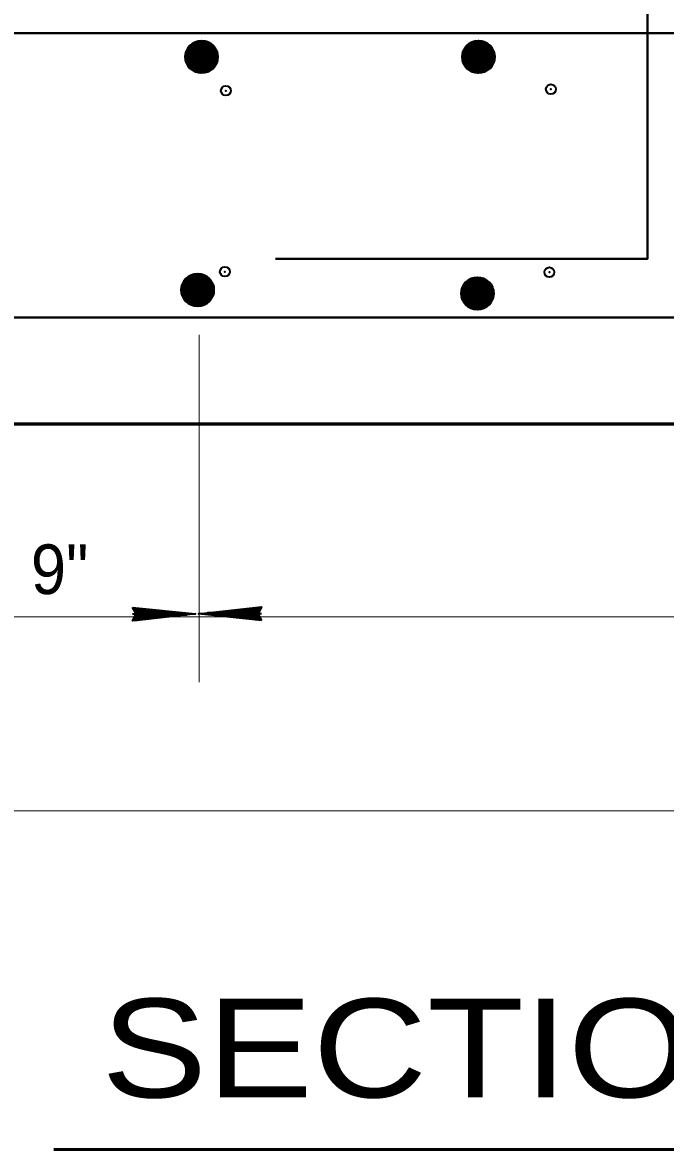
# Model space of a CAD drawing. Extents: x 4.49 to 7.69, y 0.28 to 2.27.
# Drawn here: x 5.8557 to 5.9637, y 1.2921 to 1.4815 of the extents above; entities that cross this region are included whole.
import ezdxf
from ezdxf.enums import TextEntityAlignment as Align

# ---------------------------------------------------------------- set-up
doc = ezdxf.new("R2010")
doc.units = 0
doc.header["$LTSCALE"] = 0.0033
doc.header["$PDMODE"] = 32
doc.header["$PDSIZE"] = 0.00165
doc.layers.add('1', color=7, linetype='Continuous', lineweight=35)

msp = doc.modelspace()

# ---------------------------------------------------------------- linework, layer by layer
at = {"layer": '1', "lineweight": 40}
for p, q in [((5.836083, 1.479667), (6.217, 1.479667)), ((5.883667, 1.47725), (5.88825, 1.475083)), ((5.884, 1.47725), (5.887917, 1.476583)), ((5.884083, 1.477583), (5.887917, 1.476917)), ((5.886, 1.47675), (5.887333, 1.47775)), ((5.888083, 1.476917), (5.886833, 1.478083)), ((5.930167, 1.47725), (5.93475, 1.475083)), ((5.9305, 1.47725), (5.934417, 1.476583)), ((5.930583, 1.477583), (5.934417, 1.476917)), ((5.9325, 1.47675), (5.933833, 1.47775)), ((5.934583, 1.476917), (5.933333, 1.478083)), ((5.883667, 1.475417), (5.887583, 1.474667)), ((5.88375, 1.475833), (5.887583, 1.475083)), ((5.88375, 1.475667), (5.887583, 1.474917)), ((5.883833, 1.47625), (5.887667, 1.475583)), ((5.883833, 1.476083), (5.887667, 1.475333)), ((5.883917, 1.476833), (5.887833, 1.476083)), ((5.883917, 1.476667), (5.887833, 1.475917)), ((5.883917, 1.476417), (5.88775, 1.475667)), ((5.884, 1.477083), (5.887917, 1.476333)), ((5.930167, 1.475417), (5.934083, 1.474667)), ((5.93025, 1.475833), (5.934083, 1.475083)), ((5.93025, 1.475667), (5.934083, 1.474917)), ((5.930333, 1.47625), (5.934167, 1.475583)), ((5.930333, 1.476083), (5.934167, 1.475333)), ((5.930417, 1.476833), (5.934333, 1.476083)), ((5.930417, 1.476667), (5.934333, 1.475917)), ((5.930417, 1.476417), (5.93425, 1.475667)), ((5.9305, 1.477083), (5.934417, 1.476333)), ((5.8835, 1.4745), (5.887333, 1.47375)), ((5.8835, 1.474333), (5.887333, 1.473583)), ((5.883583, 1.475), (5.8875, 1.47425)), ((5.883583, 1.474833), (5.887417, 1.474083)), ((5.883583, 1.474583), (5.887417, 1.473917)), ((5.887833, 1.474083), (5.884083, 1.473667)), ((5.93, 1.4745), (5.933833, 1.47375)), ((5.93, 1.474333), (5.933833, 1.473583)), ((5.930083, 1.475), (5.934, 1.47425)), ((5.930083, 1.474833), (5.933917, 1.474083)), ((5.930083, 1.474583), (5.933917, 1.473917)), ((5.934333, 1.474083), (5.930583, 1.473667)), ((5.883, 1.438083), (5.887583, 1.435917)), ((5.88325, 1.437667), (5.887167, 1.436917)), ((5.88325, 1.4375), (5.887167, 1.43675)), ((5.883333, 1.438083), (5.88725, 1.437417)), ((5.883333, 1.437917), (5.88725, 1.437167)), ((5.883417, 1.438417), (5.88725, 1.43775)), ((5.885333, 1.437583), (5.886667, 1.438583)), ((5.887417, 1.43775), (5.886167, 1.438917)), ((5.93, 1.4375), (5.934583, 1.435333)), ((5.930333, 1.4375), (5.93425, 1.436833)), ((5.930417, 1.437833), (5.93425, 1.437167)), ((5.932333, 1.437), (5.933667, 1.438)), ((5.934417, 1.437167), (5.933167, 1.438333)), ((5.882917, 1.435833), (5.886833, 1.435083)), ((5.882917, 1.435667), (5.88675, 1.434917)), ((5.883, 1.43625), (5.886917, 1.4355)), ((5.883083, 1.436667), (5.886917, 1.435917)), ((5.883083, 1.4365), (5.886917, 1.43575)), ((5.883167, 1.437083), (5.887, 1.436417)), ((5.883167, 1.436917), (5.887, 1.436167)), ((5.88325, 1.43725), (5.887083, 1.4365)), ((5.93, 1.435667), (5.933917, 1.434917)), ((5.930083, 1.436083), (5.933917, 1.435333)), ((5.930083, 1.435917), (5.933917, 1.435167)), ((5.930167, 1.4365), (5.934, 1.435833)), ((5.930167, 1.436333), (5.934, 1.435583)), ((5.93025, 1.437083), (5.934167, 1.436333)), ((5.93025, 1.436917), (5.934167, 1.436167)), ((5.93025, 1.436667), (5.934083, 1.435917)), ((5.930333, 1.437333), (5.93425, 1.436583)), ((5.882833, 1.435333), (5.886667, 1.434583)), ((5.882833, 1.435167), (5.886667, 1.434417)), ((5.882917, 1.435417), (5.88675, 1.43475)), ((5.887167, 1.434917), (5.883417, 1.4345)), ((5.929833, 1.43475), (5.933667, 1.434)), ((5.929833, 1.434583), (5.933667, 1.433833)), ((5.929917, 1.43525), (5.933833, 1.4345)), ((5.929917, 1.435083), (5.93375, 1.434333)), ((5.929917, 1.434833), (5.93375, 1.434167)), ((5.934167, 1.434333), (5.930417, 1.433917)), ((5.836083, 1.431917), (6.216583, 1.431917))]:
    msp.add_line(p, q, dxfattribs=at)
at = {"layer": '1', "lineweight": 60}
for p, q in [((5.883917, 1.47725), (5.88375, 1.474333)), ((5.884167, 1.47725), (5.883917, 1.474333)), ((5.884333, 1.47725), (5.884167, 1.47425)), ((5.8845, 1.47725), (5.88425, 1.47425)), ((5.884667, 1.47725), (5.8845, 1.47425)), ((5.884917, 1.47725), (5.88475, 1.47425)), ((5.885167, 1.47725), (5.884917, 1.47425)), ((5.88525, 1.477167), (5.885083, 1.47425)), ((5.885417, 1.477167), (5.88525, 1.47425)), ((5.885583, 1.477167), (5.885417, 1.47425)), ((5.885833, 1.477167), (5.885583, 1.47425)), ((5.886, 1.477167), (5.885833, 1.47425)), ((5.930417, 1.47725), (5.93025, 1.474333)), ((5.930667, 1.47725), (5.930417, 1.474333)), ((5.930833, 1.47725), (5.930667, 1.47425)), ((5.931, 1.47725), (5.93075, 1.47425)), ((5.931167, 1.47725), (5.931, 1.47425)), ((5.931417, 1.47725), (5.93125, 1.47425)), ((5.931667, 1.47725), (5.931417, 1.47425)), ((5.93175, 1.477167), (5.931583, 1.47425)), ((5.931917, 1.477167), (5.93175, 1.47425)), ((5.932083, 1.477167), (5.931917, 1.47425)), ((5.932333, 1.477167), (5.932083, 1.47425)), ((5.9325, 1.477167), (5.932333, 1.47425)), ((5.88625, 1.477083), (5.886, 1.474167)), ((5.8865, 1.477083), (5.88625, 1.474167)), ((5.886667, 1.477083), (5.8865, 1.474167)), ((5.88675, 1.477083), (5.886583, 1.474167)), ((5.886917, 1.477083), (5.88675, 1.474167)), ((5.887, 1.477083), (5.886833, 1.474167)), ((5.88725, 1.477), (5.887, 1.474083)), ((5.887417, 1.477), (5.88725, 1.474083)), ((5.887583, 1.477), (5.887333, 1.474083)), ((5.88775, 1.477), (5.887583, 1.474083)), ((5.888, 1.477), (5.887833, 1.474083)), ((5.88825, 1.475083), (5.888083, 1.476917)), ((5.93275, 1.477083), (5.9325, 1.474167)), ((5.933, 1.477083), (5.93275, 1.474167)), ((5.933167, 1.477083), (5.933, 1.474167)), ((5.93325, 1.477083), (5.933083, 1.474167)), ((5.933417, 1.477083), (5.93325, 1.474167)), ((5.9335, 1.477083), (5.933333, 1.474167)), ((5.93375, 1.477), (5.9335, 1.474083)), ((5.933917, 1.477), (5.93375, 1.474083)), ((5.934083, 1.477), (5.933833, 1.474083)), ((5.93425, 1.477), (5.934083, 1.474083)), ((5.9345, 1.477), (5.934333, 1.474083)), ((5.93475, 1.475083), (5.934583, 1.476917)), ((5.88825, 1.475083), (5.8835, 1.474333)), ((5.93475, 1.475083), (5.93, 1.474333)), ((5.88325, 1.438083), (5.883083, 1.435167)), ((5.8835, 1.438083), (5.88325, 1.435167)), ((5.883667, 1.438083), (5.8835, 1.435083)), ((5.883833, 1.438083), (5.883583, 1.435083)), ((5.884, 1.438083), (5.883833, 1.435083)), ((5.88425, 1.438083), (5.884083, 1.435083)), ((5.8845, 1.438083), (5.88425, 1.435083)), ((5.884583, 1.438), (5.884417, 1.435083)), ((5.88475, 1.438), (5.884583, 1.435083)), ((5.884917, 1.438), (5.88475, 1.435083)), ((5.885167, 1.438), (5.884917, 1.435083)), ((5.885333, 1.438), (5.885167, 1.435083)), ((5.885583, 1.437917), (5.885333, 1.435)), ((5.885833, 1.437917), (5.885583, 1.435)), ((5.886, 1.437917), (5.885833, 1.435)), ((5.886083, 1.437917), (5.885917, 1.435)), ((5.88625, 1.437917), (5.886083, 1.435)), ((5.886333, 1.437917), (5.886167, 1.435)), ((5.886583, 1.437833), (5.886333, 1.434917)), ((5.88675, 1.437833), (5.886583, 1.434917)), ((5.886917, 1.437833), (5.886667, 1.434917)), ((5.887083, 1.437833), (5.886917, 1.434917)), ((5.887333, 1.437833), (5.887167, 1.434917)), ((5.887583, 1.435917), (5.887417, 1.43775)), ((5.93025, 1.4375), (5.930083, 1.434583)), ((5.9305, 1.4375), (5.93025, 1.434583)), ((5.930667, 1.4375), (5.9305, 1.4345)), ((5.930833, 1.4375), (5.930583, 1.4345)), ((5.931, 1.4375), (5.930833, 1.4345)), ((5.93125, 1.4375), (5.931083, 1.4345)), ((5.9315, 1.4375), (5.93125, 1.4345)), ((5.931583, 1.437417), (5.931417, 1.4345)), ((5.93175, 1.437417), (5.931583, 1.4345)), ((5.931917, 1.437417), (5.93175, 1.4345)), ((5.932167, 1.437417), (5.931917, 1.4345)), ((5.932333, 1.437417), (5.932167, 1.4345)), ((5.887583, 1.435917), (5.882833, 1.435167)), ((5.932583, 1.437333), (5.932333, 1.434417)), ((5.932833, 1.437333), (5.932583, 1.434417)), ((5.933, 1.437333), (5.932833, 1.434417)), ((5.933083, 1.437333), (5.932917, 1.434417)), ((5.93325, 1.437333), (5.933083, 1.434417)), ((5.933333, 1.437333), (5.933167, 1.434417)), ((5.933583, 1.43725), (5.933333, 1.434333)), ((5.93375, 1.43725), (5.933583, 1.434333)), ((5.933917, 1.43725), (5.933667, 1.434333)), ((5.934083, 1.43725), (5.933917, 1.434333)), ((5.934333, 1.43725), (5.934167, 1.434333)), ((5.934583, 1.435333), (5.934417, 1.437167)), ((5.934583, 1.435333), (5.929833, 1.434583))]:
    msp.add_line(p, q, dxfattribs=at)
at = {"layer": '1', "lineweight": 13}
for p, q in [((5.885333, 1.429), (5.885333, 1.370583)), ((5.835917, 1.381583), (6.216917, 1.381583)), ((5.81825, 1.349), (6.234583, 1.349))]:
    msp.add_line(p, q, dxfattribs=at)
at = {"layer": '1'}
for p, q in [((5.874417, 1.383083), (5.88225, 1.382167)), ((5.874417, 1.383083), (5.88225, 1.382167)), ((5.874417, 1.383), (5.88225, 1.382167)), ((5.874417, 1.382917), (5.88225, 1.382083)), ((5.874417, 1.382917), (5.88225, 1.381917)), ((5.895583, 1.383167), (5.88825, 1.382333)), ((5.895583, 1.383), (5.88825, 1.38225)), ((5.895583, 1.382917), (5.88825, 1.382083)), ((5.895667, 1.38275), (5.888333, 1.382)), ((5.874167, 1.382083), (5.88475, 1.382083)), ((5.874333, 1.381417), (5.881667, 1.382167)), ((5.874417, 1.38125), (5.88175, 1.382083)), ((5.874417, 1.381167), (5.88175, 1.381917)), ((5.874417, 1.381), (5.88175, 1.381833)), ((5.895833, 1.382083), (5.88525, 1.382083)), ((5.895583, 1.38125), (5.88775, 1.38225)), ((5.895583, 1.38125), (5.88775, 1.382083)), ((5.895583, 1.381083), (5.88775, 1.382)), ((5.895583, 1.381083), (5.88775, 1.382)), ((5.895583, 1.381167), (5.88775, 1.382))]:
    msp.add_line(p, q, dxfattribs=at)
at = {"layer": '1', "lineweight": 53}
msp.add_line((5.860917, 1.292083), (6.198583, 1.292083), dxfattribs=at)
at = {"layer": '1', "lineweight": 40}
for points in [[(5.898167, 1.44175), (5.960667, 1.44175), (5.960667, 1.553917)], [(5.8835, 1.474333), (5.885583, 1.473083), (5.887333, 1.473583), (5.88825, 1.475083)], [(5.93, 1.474333), (5.932083, 1.473083), (5.933833, 1.473583), (5.93475, 1.475083)], [(5.882833, 1.435167), (5.884917, 1.433917), (5.886667, 1.434417), (5.887583, 1.435917)], [(5.929833, 1.434583), (5.931917, 1.433333), (5.933667, 1.433833), (5.934583, 1.435333)]]:
    msp.add_lwpolyline(points, dxfattribs=at)
at = {"layer": '1', "lineweight": 60}
for points in [[(5.81825, 1.497333), (5.81825, 1.414), (6.234917, 1.414), (6.234917, 1.497333)], [(5.883083, 1.475583), (5.88825, 1.47625), (5.883667, 1.47725)], [(5.887333, 1.473583), (5.887333, 1.47775), (5.885667, 1.473083), (5.886167, 1.47825), (5.884083, 1.473667), (5.884833, 1.478167), (5.886417, 1.473167), (5.88325, 1.4765), (5.888083, 1.476917), (5.884833, 1.47325), (5.886833, 1.478083), (5.883667, 1.47725), (5.8835, 1.474333)], [(5.884083, 1.473667), (5.885583, 1.475917), (5.883417, 1.476833), (5.885417, 1.47825), (5.885583, 1.476), (5.88725, 1.473667), (5.88325, 1.476), (5.886, 1.47675)], [(5.886833, 1.478083), (5.885583, 1.475917), (5.887833, 1.474083)], [(5.929583, 1.475583), (5.93475, 1.47625), (5.930167, 1.47725)], [(5.933833, 1.473583), (5.933833, 1.47775), (5.932167, 1.473083), (5.932667, 1.47825), (5.930583, 1.473667), (5.931333, 1.478167), (5.932917, 1.473167), (5.92975, 1.4765), (5.934583, 1.476917), (5.931333, 1.47325), (5.933333, 1.478083), (5.930167, 1.47725), (5.93, 1.474333)], [(5.930583, 1.473667), (5.932083, 1.475917), (5.929917, 1.476833), (5.931917, 1.47825), (5.932083, 1.476), (5.93375, 1.473667), (5.92975, 1.476), (5.9325, 1.47675)], [(5.933333, 1.478083), (5.932083, 1.475917), (5.934333, 1.474083)], [(5.882417, 1.436417), (5.887583, 1.437083), (5.883, 1.438083)], [(5.886667, 1.434417), (5.886667, 1.438583), (5.885, 1.433917), (5.8855, 1.439083), (5.883417, 1.4345), (5.884167, 1.439), (5.88575, 1.434), (5.882583, 1.437333), (5.887417, 1.43775), (5.884167, 1.434083), (5.886167, 1.438917), (5.883, 1.438083), (5.882833, 1.435167)], [(5.883417, 1.4345), (5.884917, 1.43675), (5.88275, 1.437667), (5.88475, 1.439083), (5.884917, 1.436833), (5.886583, 1.4345), (5.882583, 1.436833), (5.885333, 1.437583)], [(5.886167, 1.438917), (5.884917, 1.43675), (5.887167, 1.434917)], [(5.929417, 1.435833), (5.934583, 1.4365), (5.93, 1.4375)], [(5.933667, 1.433833), (5.933667, 1.438), (5.932, 1.433333), (5.9325, 1.4385), (5.930417, 1.433917), (5.931167, 1.438417), (5.93275, 1.433417), (5.929583, 1.43675), (5.934417, 1.437167), (5.931167, 1.4335), (5.933167, 1.438333), (5.93, 1.4375), (5.929833, 1.434583)], [(5.930417, 1.433917), (5.931917, 1.436167), (5.92975, 1.437083), (5.93175, 1.4385), (5.931917, 1.43625), (5.933583, 1.433917), (5.929583, 1.43625), (5.932333, 1.437)], [(5.933167, 1.438333), (5.931917, 1.436167), (5.934167, 1.434333)]]:
    msp.add_lwpolyline(points, dxfattribs=at)
at = {"layer": '1'}
for points in [[(5.874167, 1.383167), (5.88475, 1.382083), (5.874167, 1.380917), (5.87475, 1.382083)], [(5.874917, 1.382167), (5.879583, 1.38225), (5.879583, 1.382167), (5.878667, 1.382167), (5.874917, 1.38225), (5.877917, 1.382333), (5.87475, 1.382417), (5.877, 1.3825), (5.87475, 1.382583), (5.87825, 1.382333), (5.882917, 1.382167), (5.882, 1.381917), (5.88325, 1.381917), (5.874917, 1.381917), (5.877333, 1.38175), (5.87475, 1.38175), (5.880083, 1.382167), (5.87475, 1.3815)], [(5.895833, 1.381), (5.88525, 1.382083), (5.895833, 1.38325), (5.89525, 1.382083)], [(5.895083, 1.382), (5.890417, 1.381917), (5.890417, 1.382), (5.891333, 1.382), (5.895083, 1.381917), (5.892083, 1.381833), (5.89525, 1.38175), (5.893, 1.381667), (5.89525, 1.381583), (5.89175, 1.381833), (5.887083, 1.382), (5.888, 1.38225), (5.88675, 1.38225), (5.895083, 1.38225), (5.892667, 1.382417), (5.89525, 1.382417), (5.889917, 1.382), (5.89525, 1.382667)]]:
    msp.add_lwpolyline(points, close=True, dxfattribs=at)
for points in [[(5.874917, 1.382167), (5.8745, 1.382917), (5.87475, 1.382667), (5.874917, 1.382333), (5.875167, 1.382417), (5.875, 1.38275), (5.874833, 1.382), (5.874667, 1.3815), (5.874417, 1.381083)], [(5.895083, 1.382), (5.8955, 1.38125), (5.89525, 1.3815), (5.895083, 1.381833), (5.894833, 1.38175), (5.895, 1.381417), (5.895167, 1.382167), (5.895333, 1.382667), (5.895583, 1.383083)]]:
    msp.add_lwpolyline(points, dxfattribs=at)
at = {"layer": '1', "lineweight": 60}
for centre in [(5.88575, 1.475683), (5.93225, 1.475683), (5.885083, 1.436517), (5.932083, 1.435933)]:
    msp.add_circle(centre, 0.00264, dxfattribs=at)
at = {"layer": '1'}
for p in [(5.88525, 1.475083), (5.932333, 1.47525), (5.889833, 1.47), (5.944417, 1.47025), (5.889667, 1.439583), (5.944167, 1.4395), (5.885167, 1.435167), (5.932167, 1.435167)]:
    msp.add_point(p, dxfattribs=at)

# ---------------------------------------------------------------- texts
at = {"layer": '1', "width": 0.95}
msp.add_text('9"', height=0.008334, dxfattribs=at).set_placement((5.861917, 1.385417), align=Align.CENTER)
at = {"layer": '1', "width": 1.2}
msp.add_text("SECTION 'B-B' (RANGE II)", height=0.01658, dxfattribs=at).set_placement((5.868917, 1.300833))

doc.saveas('drawing.dxf')
